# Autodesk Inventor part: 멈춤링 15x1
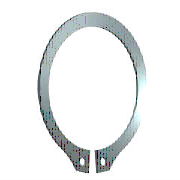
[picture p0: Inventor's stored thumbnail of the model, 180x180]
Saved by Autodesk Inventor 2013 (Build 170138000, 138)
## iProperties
Created: 2015-09
Part Number: 멈춤링 15x1
Material: 강, 연강
Description: 리테이닝 링(C형)
Document SubType Name: Modeling
Standard: KS B 1336
Designer: mm
Standards Organization: KS
Language: ko-KR
Size Designation: 15 x 1
Categories: <MemberInstance><Categories><Category DisplayName="샤프트 부품" InternalName="7f7aeb1f-a693-4053-b835-cee3144e0d98" Mnemonic="SHFT"><Category DisplayName="써클립" Inter
Density: 1 g/cm^3
IsCustomPart: 1
Author: mduedu
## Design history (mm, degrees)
sketch "스케치1"
  geometry: L1 (-6, 0)-(6, 0) reference; L2 (0, 20.189)-(0, -80.536) reference; L3 (-48.09, 0)-(48.09, 0) reference; L4 (-0.425, -14.637)-(-0.425, -18.137); L5 (-0.425, -6.54)-(-0.425, -13.29); L6 (-2.795, 2.1)-(3.672, 2.1); L7 (0.425, -6.54)-(0.425, -13.29); L8 (0.425, -14.637)-(0.425, -18.137); C1 r 0.85 at (-1.7, -16.283); C2 r 0.85 at (1.7, -16.283); A1 r 7.15 centre (0, -7.5) between (0.425, -14.637) and (-0.425, -14.637); A2 r 9.075 centre (0, -6.975) between (4.291, -14.971) and (-4.291, -14.971); A3 r 10.646 centre (0, -7.5) between (-2.023, -17.952) and (-0.425, -18.137); A4 r 1.7 centre (-1.7, -16.283) between (-3.397, -16.376) and (-2.023, -17.952); A5 r 1.7 centre (-5.095, -16.469) between (-3.397, -16.376) and (-4.291, -14.971); A6 r 1.7 centre (5.095, -16.469) between (4.291, -14.971) and (3.397, -16.376); A7 r 1.7 centre (1.7, -16.283) between (2.023, -17.952) and (3.397, -16.376); A8 r 10.646 centre (0, -7.5) between (0.425, -18.137) and (2.023, -17.952)
  constraints: 16 point on circle, 12 end point, 10 centre point, 9 symmetric about line, 5 point on line, 4 tangent, 3 coincident, 2 horizontal, 1 perpendicular, 1 vertical, 5 other
  dimensions: "d0" = 14.3 diameter of A1 (= ND); "d1" = 3.5 distance of L4.end L4.start (= SRB2); "d6" = 0.425 distance between parallel lines of L2 L5 (= 0.25 x SD5); "d7" = 2.1 distance between parallel lines of L6 L3 (= SRB1); "d8" = 0.525 distance of A1.centre A2.centre (= 0.25 x SRB1); "d9" = 1.7 radius of A4 (= SD5); "d10" = 1.7 radius of A5 (= SD5); "d11" = 1.275 distance from line of L4 A4.centre (= 0.75 x SD5); "d12" = 1.7 diameter of C1 (= SD5); "d13" = 1.7 diameter of C2 (= SD5); "d14" = 7.5 distance from line of A1.centre L1 (= 0.5 x WD)
extrude "본체" new body sketch "스케치1" distance "d2" = 1 (= SD); taper "d3" = 0 deg
workaxis "Work Axis1"
workplane "Work Plane1"
body "Solid1"
other parameters: "WD" = 15 (= WDMIN) [user parameter; used in 1 equation term], "SD" = 1 [user parameter; used in 1 equation term], "SRB1" = 2.1 [user parameter; used in 2 equation terms], "ND" = 14.3 [user parameter; used in 1 equation term], "SRB2" = 3.5 [user parameter; used in 1 equation term], "SD5" = 1.7 [user parameter; used in 6 equation terms], "d15" = 0, "d16" = 0, "d17" = 0, "d41" = 0, "d42" = 0, "WDMIN" = 15 [user parameter; used in 1 equation term], "SD3" = 13.8 [user parameter], "WDMAX" = 16 [user parameter]
